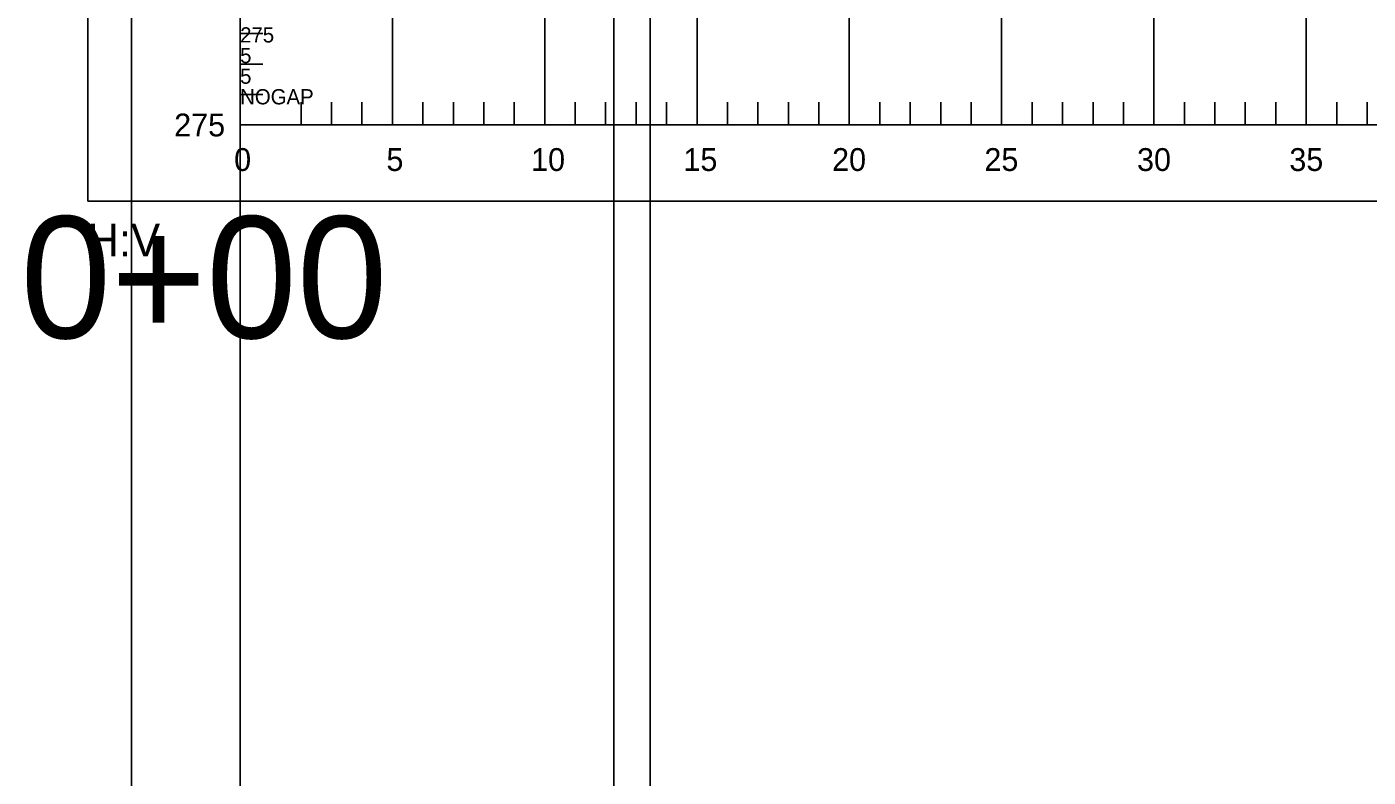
# Model space of a CAD drawing. Extents: x 1578769 to 1579225, y 724002 to 724828.
# Drawn here: x 1578820.76 to 1578864.8, y 724505.56 to 724530.2 of the extents above; entities that cross this region are included whole.
import ezdxf

# ---------------------------------------------------------------- set-up
doc = ezdxf.new("R2010")
doc.units = 0
for name, color, linetype in [('1', 7, 'Continuous'), ('Default', 7, 'Continuous'), ('Old_Level_1', 7, 'Continuous'), ('Old_Level_41', 7, 'Continuous'), ('Old_Level_42', 7, 'Continuous')]:
    doc.layers.add(name, color=color, linetype=linetype)

msp = doc.modelspace()

# ---------------------------------------------------------------- linework, layer by layer
at = {"layer": 'Default'}
for p, q in [((1578827.766, 724526.976), (1578827.766, 724776.976)), ((1578841.23, 724437.474), (1578841.23, 724687.474)), ((1578840.032, 724387.146), (1578840.032, 724637.146)), ((1578824.194, 724303.15), (1578824.194, 724553.15)), ((1578827.766, 724526.976), (1579127.766, 724526.976)), ((1578827.766, 724526.976), (1578827.766, 724276.976))]:
    msp.add_line(p, q, dxfattribs=at)
at = {"layer": 'Old_Level_1'}
for points in [[(1578822.766, 724559.476), (1578930.266, 724559.476), (1578930.266, 724524.476), (1578822.766, 724524.476)], [(1578827.766, 724556.976), (1578927.766, 724556.976), (1578927.766, 724526.976), (1578827.766, 724526.976)]]:
    msp.add_lwpolyline(points, close=True, dxfattribs=at)
at = {"layer": 'Old_Level_41'}
for p, q in [((1578832.766, 724526.976), (1578832.766, 724556.976)), ((1578837.766, 724556.976), (1578837.766, 724526.976)), ((1578842.766, 724526.976), (1578842.766, 724556.976)), ((1578847.766, 724556.976), (1578847.766, 724526.976)), ((1578852.766, 724526.976), (1578852.766, 724556.976)), ((1578857.766, 724556.976), (1578857.766, 724526.976)), ((1578862.766, 724526.976), (1578862.766, 724556.976)), ((1578827.766, 724554.476), (1578827.766, 724526.976))]:
    msp.add_line(p, q, dxfattribs=at)
at = {"layer": 'Old_Level_42'}
for p, q in [((1578827.766, 724529.976), (1578828.516, 724529.976)), ((1578827.766, 724528.976), (1578828.516, 724528.976)), ((1578827.766, 724527.976), (1578828.516, 724527.976)), ((1578829.766, 724527.726), (1578829.766, 724526.976)), ((1578830.766, 724527.726), (1578830.766, 724526.976)), ((1578831.766, 724527.726), (1578831.766, 724526.976)), ((1578833.766, 724527.726), (1578833.766, 724526.976)), ((1578834.766, 724527.726), (1578834.766, 724526.976)), ((1578835.766, 724527.726), (1578835.766, 724526.976)), ((1578836.766, 724527.726), (1578836.766, 724526.976)), ((1578838.766, 724527.726), (1578838.766, 724526.976)), ((1578839.766, 724527.726), (1578839.766, 724526.976)), ((1578840.766, 724527.726), (1578840.766, 724526.976)), ((1578841.766, 724527.726), (1578841.766, 724526.976)), ((1578843.766, 724527.726), (1578843.766, 724526.976)), ((1578844.766, 724527.726), (1578844.766, 724526.976)), ((1578845.766, 724527.726), (1578845.766, 724526.976)), ((1578846.766, 724527.726), (1578846.766, 724526.976)), ((1578848.766, 724527.726), (1578848.766, 724526.976)), ((1578849.766, 724527.726), (1578849.766, 724526.976)), ((1578850.766, 724527.726), (1578850.766, 724526.976)), ((1578851.766, 724527.726), (1578851.766, 724526.976)), ((1578853.766, 724527.726), (1578853.766, 724526.976)), ((1578854.766, 724527.726), (1578854.766, 724526.976)), ((1578855.766, 724527.726), (1578855.766, 724526.976)), ((1578856.766, 724527.726), (1578856.766, 724526.976)), ((1578858.766, 724527.726), (1578858.766, 724526.976)), ((1578859.766, 724527.726), (1578859.766, 724526.976)), ((1578860.766, 724527.726), (1578860.766, 724526.976)), ((1578861.766, 724527.726), (1578861.766, 724526.976)), ((1578863.766, 724527.726), (1578863.766, 724526.976)), ((1578864.766, 724527.726), (1578864.766, 724526.976))]:
    msp.add_line(p, q, dxfattribs=at)

# ---------------------------------------------------------------- texts
at = {"layer": '1'}
for s, p in [('275', (1578825.6, 724526.601)), ('0', (1578827.569, 724525.466)), ('5', (1578832.569, 724525.466)), ('10', (1578837.318, 724525.466)), ('15', (1578842.318, 724525.466)), ('20', (1578847.2, 724525.466)), ('25', (1578852.2, 724525.466)), ('30', (1578857.211, 724525.466)), ('35', (1578862.211, 724525.466))]:
    msp.add_text(s, height=0.75, dxfattribs=at).set_placement(p)
at = {"layer": 'Default'}
for s, height, p in [('275', 0.5, (1578827.766, 724529.685)), ('5', 0.5, (1578827.766, 724529.008)), ('5', 0.5, (1578827.766, 724528.33)), ('NOGAP', 0.5, (1578827.766, 724527.653)), ('0+00', 4, (1578820.554, 724519.976))]:
    msp.add_text(s, height=height, dxfattribs=at).set_placement(p)
at = {"layer": 'Old_Level_1'}
msp.add_text('H:V', height=1.0714, dxfattribs=at).set_placement((1578822.75, 724522.659))

doc.saveas('drawing.dxf')
